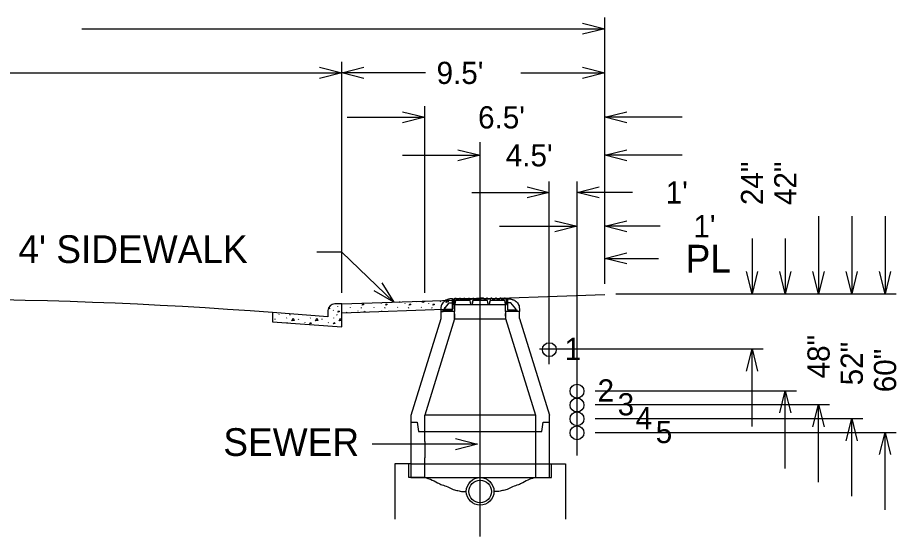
# Model space of a CAD drawing. Extents: x 524397 to 525117, y 3701341 to 3701821.
# Drawn here: x 524790.7 to 524854.2, y 3701625.9 to 3701663.4 of the extents above; entities that cross this region are included whole.
import ezdxf

# ---------------------------------------------------------------- set-up
doc = ezdxf.new("R2010")
doc.units = 0
doc.layers.add('Level 11', color=7, linetype='Continuous')

msp = doc.modelspace()

# ---------------------------------------------------------------- linework, layer by layer
at = {"layer": 'Level 11'}
for p, q in [((524833.111, 3701644.173), (524833.111, 3701663.381)), ((524831.51, 3701662.981), (524833.111, 3701662.581)), ((524795.346, 3701662.581), (524833.111, 3701662.581)), ((524833.111, 3701662.581), (524831.51, 3701662.181)), ((524812.514, 3701659.792), (524814.115, 3701659.392)), ((524814.115, 3701643.51), (524814.115, 3701660.192)), ((524814.115, 3701659.392), (524815.716, 3701659.792)), ((524831.51, 3701659.792), (524833.111, 3701659.392)), ((524833.111, 3701644.173), (524833.111, 3701660.192)), ((524785.769, 3701659.392), (524814.115, 3701659.392)), ((524814.115, 3701659.392), (524812.514, 3701658.991)), ((524820.165, 3701659.392), (524814.115, 3701659.392)), ((524815.716, 3701658.991), (524814.115, 3701659.392)), ((524827.061, 3701659.392), (524833.111, 3701659.392)), ((524833.111, 3701659.392), (524831.51, 3701658.991)), ((524818.51, 3701656.583), (524820.111, 3701656.183)), ((524820.111, 3701643.789), (524820.111, 3701656.983)), ((524833.111, 3701644.243), (524833.111, 3701656.983)), ((524833.111, 3701656.183), (524834.712, 3701656.583)), ((524814.507, 3701656.183), (524820.111, 3701656.183)), ((524820.111, 3701656.183), (524818.51, 3701655.782)), ((524838.714, 3701656.183), (524833.111, 3701656.183)), ((524834.712, 3701655.782), (524833.111, 3701656.183)), ((524820.111, 3701643.504), (524820.111, 3701655.285)), ((524824.111, 3701625.93), (524824.111, 3701654.399)), ((524818.507, 3701653.443), (524824.111, 3701653.443)), ((524822.51, 3701653.843), (524824.111, 3701653.443)), ((524824.111, 3701653.443), (524822.51, 3701653.043)), ((524833.111, 3701653.443), (524834.712, 3701653.843)), ((524838.714, 3701653.443), (524833.111, 3701653.443)), ((524834.712, 3701653.043), (524833.111, 3701653.443)), ((524829.111, 3701638.364), (524829.111, 3701651.54)), ((524831.111, 3701631.776), (524831.111, 3701651.54)), ((524823.507, 3701650.763), (524829.111, 3701650.763)), ((524827.51, 3701651.163), (524829.111, 3701650.763)), ((524829.111, 3701650.763), (524827.51, 3701650.362)), ((524831.111, 3701650.763), (524832.712, 3701651.163)), ((524835.114, 3701650.763), (524831.111, 3701650.763)), ((524832.712, 3701650.362), (524831.111, 3701650.763)), ((524848.553, 3701649.046), (524848.553, 3701643.442)), ((524850.955, 3701649.046), (524850.955, 3701643.442)), ((524853.356, 3701649.046), (524853.356, 3701643.442)), ((524825.507, 3701648.321), (524831.111, 3701648.321)), ((524829.51, 3701648.721), (524831.111, 3701648.321)), ((524831.111, 3701648.321), (524829.51, 3701647.921)), ((524833.111, 3701648.321), (524834.712, 3701648.721)), ((524837.114, 3701648.321), (524833.111, 3701648.321)), ((524834.712, 3701647.921), (524833.111, 3701648.321)), ((524843.751, 3701647.445), (524843.751, 3701643.442)), ((524846.152, 3701647.445), (524846.152, 3701643.442)), ((524814.114, 3701646.458), (524812.309, 3701646.458)), ((524817.892, 3701642.847), (524814.114, 3701646.458)), ((524833.111, 3701645.996), (524834.712, 3701646.396)), ((524833.111, 3701645.996), (524836.987, 3701645.996)), ((524834.712, 3701645.596), (524833.111, 3701645.996)), ((524843.751, 3701643.442), (524843.35, 3701645.043)), ((524844.151, 3701645.043), (524843.751, 3701643.442)), ((524846.152, 3701643.442), (524845.752, 3701645.043)), ((524846.552, 3701645.043), (524846.152, 3701643.442)), ((524848.553, 3701643.442), (524848.153, 3701645.043)), ((524848.954, 3701645.043), (524848.553, 3701643.442)), ((524850.955, 3701643.442), (524850.555, 3701645.043)), ((524851.355, 3701645.043), (524850.955, 3701643.442)), ((524853.356, 3701643.442), (524852.956, 3701645.043)), ((524853.756, 3701645.043), (524853.356, 3701643.442)), ((524817.011, 3701644.243), (524817.892, 3701642.847)), ((524817.892, 3701642.847), (524816.458, 3701643.664)), ((524833.111, 3701643.373), (524822.111, 3701642.989)), ((524822.112, 3701643.087), (524822.112, 3701643.087)), ((524822.112, 3701643.087), (524822.196, 3701643.087)), ((524822.112, 3701642.796), (524822.112, 3701643.087)), ((524822.195, 3701642.671), (524822.196, 3701643.087)), ((524822.237, 3701643.087), (524822.237, 3701642.671)), ((524822.279, 3701643.087), (524822.237, 3701643.087)), ((524822.237, 3701643.087), (524822.279, 3701643.087)), ((524822.237, 3701642.671), (524822.237, 3701643.087)), ((524822.279, 3701643.087), (524822.295, 3701643.128)), ((524822.279, 3701643.087), (524822.295, 3701643.128)), ((524822.295, 3701643.128), (524822.357, 3701643.128)), ((524822.295, 3701643.128), (524822.357, 3701643.128)), ((524822.372, 3701643.087), (524822.357, 3701643.128)), ((524822.357, 3701643.128), (524822.372, 3701643.087)), ((524822.603, 3701643.087), (524822.372, 3701643.087)), ((524822.372, 3701643.087), (524822.603, 3701643.087)), ((524822.603, 3701643.087), (524822.618, 3701643.128)), ((524822.603, 3701643.087), (524822.618, 3701643.128)), ((524822.618, 3701643.128), (524822.678, 3701643.128)), ((524822.618, 3701643.128), (524822.678, 3701643.128)), ((524822.693, 3701643.087), (524822.678, 3701643.128)), ((524822.678, 3701643.128), (524822.693, 3701643.087)), ((524822.919, 3701643.087), (524822.693, 3701643.087)), ((524822.693, 3701643.087), (524822.919, 3701643.087)), ((524822.919, 3701643.087), (524822.934, 3701643.128)), ((524822.919, 3701643.087), (524822.934, 3701643.128)), ((524822.934, 3701643.128), (524823.002, 3701643.128)), ((524822.934, 3701643.128), (524823.002, 3701643.128)), ((524823.017, 3701643.087), (524823.002, 3701643.128)), ((524823.002, 3701643.128), (524823.017, 3701643.087)), ((524823.247, 3701643.087), (524823.017, 3701643.087)), ((524823.017, 3701643.087), (524823.247, 3701643.087)), ((524823.247, 3701643.087), (524823.262, 3701643.128)), ((524823.247, 3701643.087), (524823.262, 3701643.128)), ((524823.262, 3701643.128), (524823.327, 3701643.128)), ((524823.262, 3701643.128), (524823.327, 3701643.128)), ((524823.342, 3701643.087), (524823.327, 3701643.128)), ((524823.327, 3701643.128), (524823.342, 3701643.087)), ((524823.569, 3701643.087), (524823.342, 3701643.087)), ((524823.342, 3701643.087), (524823.569, 3701643.087)), ((524823.569, 3701643.087), (524823.584, 3701643.128)), ((524823.569, 3701643.087), (524823.584, 3701643.128)), ((524823.584, 3701643.128), (524823.643, 3701643.128)), ((524823.584, 3701643.128), (524823.643, 3701643.128)), ((524823.658, 3701643.087), (524823.643, 3701643.128)), ((524823.643, 3701643.128), (524823.658, 3701643.087)), ((524823.844, 3701643.087), (524823.658, 3701643.087)), ((524823.658, 3701643.087), (524823.844, 3701643.087)), ((524823.844, 3701643.087), (524823.86, 3701643.128)), ((524823.844, 3701643.087), (524823.86, 3701643.128)), ((524823.86, 3701643.128), (524824.111, 3701643.128)), ((524823.86, 3701643.128), (524824.362, 3701643.128)), ((524824.362, 3701643.128), (524824.111, 3701643.128)), ((524824.377, 3701643.087), (524824.362, 3701643.128)), ((524824.362, 3701643.128), (524824.377, 3701643.087)), ((524824.564, 3701643.087), (524824.377, 3701643.087)), ((524824.377, 3701643.087), (524824.564, 3701643.087)), ((524824.564, 3701643.087), (524824.579, 3701643.128)), ((524824.564, 3701643.087), (524824.579, 3701643.128)), ((524824.637, 3701643.128), (524824.579, 3701643.128)), ((524824.579, 3701643.128), (524824.637, 3701643.128)), ((524824.653, 3701643.087), (524824.637, 3701643.128)), ((524824.637, 3701643.128), (524824.653, 3701643.087)), ((524824.88, 3701643.087), (524824.653, 3701643.087)), ((524824.653, 3701643.087), (524824.88, 3701643.087)), ((524824.88, 3701643.087), (524824.895, 3701643.128)), ((524824.88, 3701643.087), (524824.895, 3701643.128)), ((524824.96, 3701643.128), (524824.895, 3701643.128)), ((524824.895, 3701643.128), (524824.96, 3701643.128)), ((524824.975, 3701643.087), (524824.96, 3701643.128)), ((524824.96, 3701643.128), (524824.975, 3701643.087)), ((524825.204, 3701643.087), (524824.975, 3701643.087)), ((524824.975, 3701643.087), (524825.204, 3701643.087)), ((524825.204, 3701643.087), (524825.219, 3701643.128)), ((524825.204, 3701643.087), (524825.219, 3701643.128)), ((524825.287, 3701643.128), (524825.219, 3701643.128)), ((524825.219, 3701643.128), (524825.287, 3701643.128)), ((524825.302, 3701643.087), (524825.287, 3701643.128)), ((524825.287, 3701643.128), (524825.302, 3701643.087)), ((524825.529, 3701643.087), (524825.302, 3701643.087)), ((524825.302, 3701643.087), (524825.529, 3701643.087)), ((524825.529, 3701643.087), (524825.544, 3701643.128)), ((524825.529, 3701643.087), (524825.544, 3701643.128)), ((524825.603, 3701643.128), (524825.544, 3701643.128)), ((524825.544, 3701643.128), (524825.603, 3701643.128)), ((524825.618, 3701643.087), (524825.603, 3701643.128)), ((524825.603, 3701643.128), (524825.618, 3701643.087)), ((524825.85, 3701643.087), (524825.618, 3701643.087)), ((524825.618, 3701643.087), (524825.672, 3701643.087)), ((524825.672, 3701643.087), (524825.672, 3701642.962)), ((524825.672, 3701643.087), (524825.672, 3701642.962)), ((524825.797, 3701643.087), (524825.797, 3701642.962)), ((524825.797, 3701643.087), (524825.85, 3701643.087)), ((524825.797, 3701642.962), (524825.797, 3701643.087)), ((524825.85, 3701643.087), (524825.865, 3701643.128)), ((524825.85, 3701643.087), (524825.865, 3701643.128)), ((524825.927, 3701643.128), (524825.865, 3701643.128)), ((524825.865, 3701643.128), (524825.927, 3701643.128)), ((524825.942, 3701643.087), (524825.927, 3701643.128)), ((524825.927, 3701643.128), (524825.942, 3701643.087)), ((524825.984, 3701643.087), (524825.942, 3701643.087)), ((524825.942, 3701643.087), (524825.984, 3701643.087)), ((524825.984, 3701643.087), (524825.984, 3701642.671)), ((524825.984, 3701643.087), (524825.984, 3701642.671)), ((524826.026, 3701642.671), (524826.026, 3701643.087)), ((524826.11, 3701643.087), (524826.026, 3701643.087)), ((524826.11, 3701642.796), (524826.11, 3701643.087)), ((524833.911, 3701643.442), (524844.551, 3701643.442)), ((524833.911, 3701643.442), (524846.952, 3701643.442)), ((524833.911, 3701643.442), (524849.354, 3701643.442)), ((524833.911, 3701643.442), (524851.755, 3701643.442)), ((524833.911, 3701643.442), (524854.157, 3701643.442)), ((524814.121, 3701642.71), (524813.608, 3701642.71)), ((524813.608, 3701642.71), (524813.621, 3701642.71)), ((524813.827, 3701642.496), (524813.841, 3701642.528)), ((524814.115, 3701642.71), (524822.111, 3701642.989)), ((524814.115, 3701642.049), (524814.115, 3701642.71)), ((524814.121, 3701641.048), (524814.121, 3701642.71)), ((524814.748, 3701642.444), (524814.762, 3701642.476)), ((524815.271, 3701642.75), (524815.273, 3701642.735)), ((524815.512, 3701642.444), (524815.526, 3701642.422)), ((524815.526, 3701642.436), (524815.54, 3701642.414)), ((524816.45, 3701642.444), (524816.464, 3701642.476)), ((524816.971, 3701642.767), (524816.974, 3701642.735)), ((524817.213, 3701642.444), (524817.228, 3701642.422)), ((524817.228, 3701642.436), (524817.242, 3701642.414)), ((524818.151, 3701642.444), (524818.165, 3701642.476)), ((524818.672, 3701642.767), (524818.676, 3701642.735)), ((524818.915, 3701642.444), (524818.929, 3701642.422)), ((524818.929, 3701642.436), (524818.943, 3701642.414)), ((524819.529, 3701642.856), (524819.544, 3701642.888)), ((524819.853, 3701642.444), (524819.867, 3701642.476)), ((524820.374, 3701642.767), (524820.377, 3701642.735)), ((524820.616, 3701642.444), (524820.631, 3701642.422)), ((524820.631, 3701642.436), (524820.645, 3701642.414)), ((524821.231, 3701642.856), (524821.245, 3701642.888)), ((524821.529, 3701642.358), (524821.879, 3701642.796)), ((524821.554, 3701642.444), (524821.568, 3701642.476)), ((524821.879, 3701642.796), (524822.112, 3701642.796)), ((524822.075, 3701642.767), (524822.079, 3701642.735)), ((524822.111, 3701642.989), (524822.134, 3701642.329)), ((524822.112, 3701642.254), (524822.112, 3701642.796)), ((524822.279, 3701642.671), (524822.195, 3701642.671)), ((524822.237, 3701642.671), (524825.984, 3701642.671)), ((524822.279, 3701642.671), (524822.237, 3701642.671)), ((524822.279, 3701642.671), (524822.33, 3701642.962)), ((524822.33, 3701642.962), (524822.279, 3701642.671)), ((524822.279, 3701642.171), (524822.279, 3701642.671)), ((524823.393, 3701642.962), (524822.33, 3701642.962)), ((524823.393, 3701642.962), (524822.33, 3701642.962)), ((524823.444, 3701642.671), (524823.393, 3701642.962)), ((524823.444, 3701642.671), (524823.393, 3701642.962)), ((524823.528, 3701642.671), (524823.444, 3701642.671)), ((524823.528, 3701642.671), (524823.58, 3701642.962)), ((524823.58, 3701642.962), (524823.528, 3701642.671)), ((524824.642, 3701642.962), (524823.58, 3701642.962)), ((524824.642, 3701642.962), (524823.58, 3701642.962)), ((524824.694, 3701642.671), (524824.642, 3701642.962)), ((524824.694, 3701642.671), (524824.642, 3701642.962)), ((524824.777, 3701642.671), (524824.694, 3701642.671)), ((524824.777, 3701642.671), (524824.828, 3701642.962)), ((524824.828, 3701642.962), (524824.777, 3701642.671)), ((524825.891, 3701642.962), (524824.828, 3701642.962)), ((524825.672, 3701642.962), (524824.828, 3701642.962)), ((524825.891, 3701642.962), (524825.797, 3701642.962)), ((524825.943, 3701642.671), (524825.891, 3701642.962)), ((524825.943, 3701642.671), (524825.891, 3701642.962)), ((524825.943, 3701642.171), (524825.943, 3701642.671)), ((524825.943, 3701642.671), (524826.026, 3701642.671)), ((524825.984, 3701642.671), (524825.943, 3701642.671)), ((524826.11, 3701642.254), (524826.11, 3701642.796)), ((524826.342, 3701642.796), (524826.11, 3701642.796)), ((524826.692, 3701642.358), (524826.342, 3701642.796)), ((524813.121, 3701641.785), (524809.121, 3701642.087)), ((524809.121, 3701642.087), (524809.121, 3701641.425)), ((524809.586, 3701641.939), (524809.6, 3701641.971)), ((524810.35, 3701641.939), (524810.364, 3701641.917)), ((524810.364, 3701641.931), (524810.378, 3701641.909)), ((524813.121, 3701642.247), (524813.121, 3701641.785)), ((524813.51, 3701642.261), (524813.514, 3701642.229)), ((524813.753, 3701641.939), (524813.767, 3701641.917)), ((524813.767, 3701641.931), (524813.781, 3701641.909)), ((524822.134, 3701642.329), (524814.115, 3701642.049)), ((524814.46, 3701642.099), (524814.475, 3701642.131)), ((524815.302, 3701642.18), (524815.316, 3701642.212)), ((524816.172, 3701642.121), (524816.176, 3701642.131)), ((524817.004, 3701642.18), (524817.018, 3701642.212)), ((524818.718, 3701642.21), (524818.719, 3701642.212)), ((524821.269, 3701642.171), (524821.269, 3701641.637)), ((524822.279, 3701642.171), (524821.269, 3701642.171)), ((524821.269, 3701642.171), (524821.446, 3701642.171)), ((524821.446, 3701642.171), (524821.446, 3701642.254)), ((524821.446, 3701642.254), (524821.529, 3701642.254)), ((524821.529, 3701642.254), (524821.529, 3701642.358)), ((524821.529, 3701642.254), (524822.112, 3701642.254)), ((524822.268, 3701641.638), (524822.268, 3701642.171)), ((524822.268, 3701642.004), (524822.268, 3701641.678)), ((524826.953, 3701642.171), (524825.943, 3701642.171)), ((524825.954, 3701642.171), (524825.954, 3701641.671)), ((524826.953, 3701642.171), (524825.954, 3701642.171)), ((524825.954, 3701641.838), (524825.954, 3701642.011)), ((524826.692, 3701642.254), (524826.11, 3701642.254)), ((524826.692, 3701642.254), (524826.692, 3701642.358)), ((524826.776, 3701642.254), (524826.692, 3701642.254)), ((524826.776, 3701642.171), (524826.776, 3701642.254)), ((524826.953, 3701642.171), (524826.776, 3701642.171)), ((524826.953, 3701641.671), (524826.953, 3701642.171)), ((524809.121, 3701641.425), (524814.121, 3701641.048)), ((524809.298, 3701641.594), (524809.312, 3701641.626)), ((524810.14, 3701641.675), (524810.154, 3701641.707)), ((524811, 3701641.594), (524811.014, 3701641.626)), ((524811.444, 3701641.366), (524811.458, 3701641.345)), ((524811.842, 3701641.675), (524811.856, 3701641.707)), ((524812.701, 3701641.594), (524812.715, 3701641.626)), ((524813.145, 3701641.366), (524813.159, 3701641.345)), ((524813.543, 3701641.675), (524813.557, 3701641.707)), ((524821.269, 3701641.637), (524819.118, 3701634.67)), ((524822.268, 3701641.638), (524820.118, 3701634.671)), ((524822.268, 3701641.638), (524825.954, 3701641.638)), ((524825.954, 3701641.671), (524828.113, 3701634.675)), ((524826.953, 3701641.671), (524829.112, 3701634.675)), ((524828.411, 3701639.471), (524844.551, 3701639.471)), ((524843.35, 3701637.87), (524843.751, 3701639.471)), ((524843.751, 3701633.867), (524843.751, 3701639.471)), ((524843.751, 3701639.471), (524844.151, 3701637.87)), ((524832.411, 3701636.442), (524846.952, 3701636.442)), ((524845.752, 3701634.841), (524846.152, 3701636.442)), ((524846.152, 3701630.839), (524846.152, 3701636.442)), ((524846.152, 3701636.442), (524846.552, 3701634.841)), ((524832.411, 3701635.442), (524849.354, 3701635.442)), ((524848.153, 3701633.841), (524848.553, 3701635.442)), ((524848.553, 3701629.839), (524848.553, 3701635.442)), ((524848.553, 3701635.442), (524848.954, 3701633.841)), ((524819.118, 3701634.67), (524819.118, 3701633.509)), ((524819.118, 3701634.377), (524819.118, 3701634.176)), ((524819.118, 3701634.176), (524819.576, 3701634.176)), ((524819.118, 3701634.176), (524819.576, 3701634.176)), ((524819.118, 3701634.176), (524819.118, 3701632.788)), ((524819.576, 3701634.176), (524819.659, 3701633.509)), ((524819.576, 3701634.176), (524819.659, 3701633.509)), ((524828.113, 3701634.675), (524820.118, 3701634.671)), ((524820.118, 3701633.509), (524820.118, 3701634.671)), ((524820.118, 3701634.176), (524820.118, 3701634.377)), ((524820.118, 3701632.788), (524820.118, 3701634.176)), ((524828.113, 3701634.675), (524828.113, 3701633.509)), ((524828.113, 3701634.675), (524828.113, 3701634.176)), ((524828.113, 3701634.377), (524828.113, 3701634.176)), ((524828.113, 3701634.377), (524828.113, 3701634.176)), ((524828.113, 3701634.176), (524828.113, 3701630.178)), ((524828.113, 3701634.176), (524828.113, 3701630.178)), ((524828.571, 3701633.509), (524828.654, 3701634.176)), ((524828.571, 3701633.509), (524828.654, 3701634.176)), ((524828.654, 3701634.176), (524829.112, 3701634.176)), ((524828.654, 3701634.176), (524829.112, 3701634.176)), ((524828.654, 3701634.176), (524829.112, 3701634.176)), ((524829.112, 3701634.176), (524829.112, 3701634.675)), ((524829.112, 3701634.176), (524829.112, 3701634.675)), ((524829.112, 3701630.178), (524829.112, 3701634.377)), ((524829.112, 3701633.509), (524829.112, 3701634.176)), ((524832.411, 3701634.442), (524851.755, 3701634.442)), ((524850.555, 3701632.841), (524850.955, 3701634.442)), ((524850.955, 3701628.839), (524850.955, 3701634.442)), ((524850.955, 3701634.442), (524851.355, 3701632.841)), ((524819.118, 3701633.788), (524819.118, 3701630.178)), ((524819.659, 3701633.509), (524820.118, 3701633.509)), ((524819.659, 3701633.509), (524820.118, 3701633.509)), ((524820.118, 3701633.509), (524828.113, 3701633.509)), ((524820.118, 3701633.509), (524828.113, 3701633.509)), ((524822.325, 3701632.992), (524823.926, 3701632.592)), ((524828.113, 3701633.509), (524828.571, 3701633.509)), ((524828.113, 3701633.509), (524828.571, 3701633.509)), ((524832.411, 3701633.442), (524854.157, 3701633.442)), ((524852.956, 3701631.841), (524853.356, 3701633.442)), ((524853.356, 3701627.839), (524853.356, 3701633.442)), ((524853.356, 3701633.442), (524853.756, 3701631.841)), ((524823.926, 3701632.592), (524816.309, 3701632.592)), ((524820.118, 3701632.788), (524820.118, 3701631.604)), ((524823.926, 3701632.592), (524822.325, 3701632.191)), ((524819.118, 3701631.178), (524817.952, 3701631.178)), ((524817.952, 3701631.178), (524817.952, 3701627.18)), ((524818.952, 3701630.178), (524818.952, 3701631.178)), ((524819.118, 3701631.178), (524829.112, 3701631.178)), ((524820.118, 3701630.178), (524820.118, 3701631.604)), ((524829.112, 3701631.178), (524830.278, 3701631.178)), ((524829.279, 3701630.178), (524829.279, 3701631.178)), ((524830.278, 3701631.178), (524830.278, 3701627.18)), ((524819.118, 3701630.178), (524818.952, 3701630.178)), ((524819.118, 3701630.178), (524818.952, 3701630.178)), ((524819.118, 3701630.178), (524820.118, 3701630.178)), ((524820.118, 3701630.178), (524819.118, 3701630.178)), ((524820.118, 3701630.178), (524819.118, 3701630.178)), ((524820.118, 3701630.178), (524828.113, 3701630.178)), ((524828.113, 3701630.178), (524829.112, 3701630.178)), ((524828.113, 3701630.178), (524829.112, 3701630.178)), ((524829.112, 3701630.178), (524829.279, 3701630.178))]:
    msp.add_line(p, q, dxfattribs=at)
for points in [[(524813.185, 3701642.456), (524813.253, 3701642.386), (524813.149, 3701642.337)], [(524815.594, 3701642.629), (524815.636, 3701642.717), (524815.707, 3701642.664), (524815.594, 3701642.629)], [(524817.295, 3701642.629), (524817.338, 3701642.717), (524817.409, 3701642.664), (524817.295, 3701642.629)], [(524818.26, 3701642.819), (524818.265, 3701642.855)], [(524818.343, 3701642.857), (524818.263, 3701642.82)], [(524818.997, 3701642.629), (524819.039, 3701642.717), (524819.11, 3701642.664), (524818.997, 3701642.629)], [(524819.962, 3701642.819), (524819.975, 3701642.914)], [(524820.09, 3701642.918), (524820.117, 3701642.891), (524819.965, 3701642.82)], [(524820.698, 3701642.629), (524820.741, 3701642.717), (524820.812, 3701642.664), (524820.698, 3701642.629)], [(524821.663, 3701642.819), (524821.684, 3701642.974)], [(524821.736, 3701642.976), (524821.818, 3701642.891), (524821.666, 3701642.82)], [(524813.834, 3701642.123), (524813.877, 3701642.212), (524813.948, 3701642.159), (524813.834, 3701642.123)], [(524814.115, 3701642.098), (524814.137, 3701642.05)], [(524815.737, 3701642.106), (524815.778, 3701642.184), (524815.812, 3701642.109)], [(524817.471, 3701642.167), (524817.48, 3701642.184), (524817.487, 3701642.167)], [(524810.151, 3701641.348), (524810.158, 3701641.363), (524810.181, 3701641.345)], [(524810.52, 3701641.498), (524810.616, 3701641.679), (524810.691, 3701641.512), (524810.524, 3701641.498)], [(524811.817, 3701641.274), (524811.859, 3701641.363), (524811.93, 3701641.309), (524811.817, 3701641.274)], [(524812.222, 3701641.498), (524812.318, 3701641.679), (524812.392, 3701641.512), (524812.225, 3701641.498)], [(524813.518, 3701641.274), (524813.561, 3701641.363), (524813.632, 3701641.309), (524813.518, 3701641.274)], [(524813.923, 3701641.498), (524814.019, 3701641.679), (524814.094, 3701641.512), (524813.927, 3701641.498)]]:
    msp.add_lwpolyline(points, dxfattribs=at)
for centre, radius in [((524829.111, 3701639.413), 0.5), ((524831.111, 3701636.413), 0.5), ((524831.111, 3701635.413), 0.5), ((524831.111, 3701634.413), 0.5), ((524831.111, 3701633.413), 0.5), ((524824.115, 3701629.179), 0.999), ((524824.115, 3701629.179), 0.814)]:
    msp.add_circle(centre, radius, dxfattribs=at)
for centre, radius, start, end in [((524783.114, 3701297.657), 345.41, 85.68192, 94.31764), ((524813.615, 3701642.215), 0.494, 89.23325, 176.29205)]:
    msp.add_arc(centre, radius, start, end, dxfattribs=at)
for points in [[(524822.112, 3701643.087), (524822.039, 3701643.086), (524821.96, 3701643.076), (524821.891, 3701643.063), (524821.832, 3701643.051), (524821.768, 3701643.024), (524821.71, 3701643.01), (524821.567, 3701642.931), (524821.463, 3701642.845), (524821.372, 3701642.726), (524821.296, 3701642.563), (524821.275, 3701642.33), (524821.269, 3701642.171)], [(524826.11, 3701643.087), (524826.182, 3701643.086), (524826.262, 3701643.076), (524826.33, 3701643.063), (524826.389, 3701643.051), (524826.453, 3701643.024), (524826.512, 3701643.01), (524826.655, 3701642.931), (524826.758, 3701642.845), (524826.849, 3701642.726), (524826.926, 3701642.563), (524826.946, 3701642.33), (524826.953, 3701642.171)], [(524820.118, 3701630.178), (524820.532, 3701630.054), (524821.035, 3701629.802), (524821.351, 3701629.655), (524821.77, 3701629.509), (524822.169, 3701629.32), (524822.505, 3701629.236), (524822.841, 3701629.173), (524823.116, 3701629.179)], [(524828.113, 3701630.178), (524827.699, 3701630.054), (524827.195, 3701629.802), (524826.88, 3701629.655), (524826.46, 3701629.509), (524826.061, 3701629.32), (524825.725, 3701629.236), (524825.389, 3701629.173), (524825.115, 3701629.179)]]:
    msp.add_spline(points, degree=3, dxfattribs=at)

# ---------------------------------------------------------------- texts
for s, height, p in [("9.5'", 1.601, (524820.966, 3701658.59)), ("6.5'", 1.601, (524823.963, 3701655.38)), ("4.5'", 1.601, (524825.964, 3701652.641)), ("1'", 1.601, (524837.515, 3701649.96)), ("1'", 1.601, (524839.515, 3701647.519)), ("4' SIDEWALK", 2, (524790.763, 3701645.667)), ('PL', 2, (524838.957, 3701644.978)), ('1', 1.601, (524830.214, 3701638.668)), ('2', 1.601, (524832.596, 3701635.668)), ('3', 1.601, (524834.046, 3701634.668)), ('4', 1.601, (524835.345, 3701633.668)), ('5', 1.601, (524836.795, 3701632.668)), ('SEWER', 2, (524805.566, 3701631.741))]:
    msp.add_text(s, height=height, dxfattribs=at).set_placement(p)
for s, p in [('24"', (524844.551, 3701649.845)), ('42"', (524846.952, 3701649.845)), ('48"', (524849.354, 3701637.335)), ('52"', (524851.755, 3701636.835)), ('60"', (524854.157, 3701636.335))]:
    msp.add_text(s, height=1.601, rotation=90, dxfattribs=at).set_placement(p)

doc.saveas('drawing.dxf')
